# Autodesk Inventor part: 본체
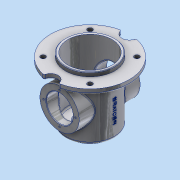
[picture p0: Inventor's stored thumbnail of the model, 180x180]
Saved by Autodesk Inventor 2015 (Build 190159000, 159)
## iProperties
Created: 2018-04
Part Number: 본체
Material: 알루미늄 6061
Document SubType Name: Modeling
Designer: SCD-A03
Density: 2.7 g/cm^3
Appearance: 알루미늄 - 평지
Mass: 1146.66 g
Surface Area: 1201.21 cm^2
Volume: 424.689 cm^3
Author: SCD-A03
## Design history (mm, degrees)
sketch "스케치1"
  geometry: C1 r 50 at (0, 0); 1 further point
  constraints: 1 centre point, 1 coincident
  dimensions: "d0" = 100 diameter of C1
extrude "돌출1" new body sketch "스케치1" distance "d1" = 128; taper "d2" = 0 deg
feature "쉘1" dims "d3" = 5
sketch "스케치2"
  geometry: C1 r 50 at (0, 0) reference; C2 r 40 at (0, 0)
  constraints: 1 centre point, 1 coincident
  dimensions: "d4" = 80 diameter of C2
extrude "돌출2" join sketch "스케치2" distance "d5" = 5; taper "d6" = 0 deg
sketch "스케치3"
  geometry: C1 r 50 at (0, 0) reference; C2 r 50 at (0, 0)
  constraints: 1 centre point, 1 coincident
  dimensions: "d7" = 100 diameter of C2
extrude "돌출3" join sketch "스케치3" distance "d8" = 8; taper "d9" = 0 deg
node "작업 평면1"
sketch "스케치4"
  geometry: C1 r 80 at (0, 0); C2 r 50 at (0, 0) reference; 1 further point
  constraints: 1 centre point, 1 coincident
  dimensions: "d11" = 160 diameter of C1
extrude "돌출4" join sketch "스케치4" distance "d12" = 10; taper "d13" = 0 deg
sketch "스케치5"
  geometry: C1 r 40 at (0, 0) reference; C2 r 27 at (0, 0)
  constraints: 1 centre point, 1 coincident
  dimensions: "d14" = 54 diameter of C2
extrude "돌출5" cut sketch "스케치5" stored distance "d15" = 10; taper "d16" = 0 deg
node "작업 평면2"
sketch "스케치6"
  geometry: L1 (-80, 120)-(80, 120) reference; L2 (0, 120)-(0, 60); C1 r 40 at (0, 60); 1 further point
  constraints: 2 end point, 1 centre point, 1 coincident, 1 midpoint, 1 vertical
  dimensions: "d18" = 60 distance of L2.start L2.end; "d19" = 80 diameter of C1
extrude "돌출6" join sketch "스케치6" stored distance "d20" = 10; taper "d21" = 0 deg
sketch "스케치7"
  geometry: C1 r 40 at (0, 0) reference; C2 r 27 at (0, 0); 1 further point
  constraints: 1 centre point, 1 coincident
  dimensions: "d22" = 54 diameter of C2
extrude "돌출7" cut sketch "스케치7" stored distance "d23" = 10; taper "d24" = 0 deg
sketch "스케치8" dims "d25" = 65
  geometry: L1 (-27, -52)-(27, -52) reference; L2 (-40, -65)-(40, -65) reference; L3 (-50, 50)-(50, 50) reference; L4 (-50, -60)-(50, -60) reference; C1 r 40 at (0, 0) reference; 7 further points
  constraints: 1 coincident, 1 vertical alignment, 8 other
  dimensions: "d28" = 360 deg dimension on point (0, 0) point (0, -32.5) (derived); "d30" = 52 distance from line of point (32.5, 0) L1
hole "구멍1" sketch "스케치8" at (0, -32.5), (32.5, 0), (0, 32.5), (-32.5, 0) diameter "d31" = 3.459; stored, may be unused: countersink angle "d35" = 90 deg, drill point angle "d37" = 118 deg; dims "d32" = 8, "d33" = 4, "d34" = 2, "d36" = 10
sketch "스케치9" dims "d38" = 65
  geometry: L1 (27, -62)-(27, -36) reference; C1 r 40 at (0, 0) reference; C2 r 80 at (0, 0) reference; C3 r 50 at (0, 0) reference; C4 r 80 at (0, 0) reference; 5 further points
  constraints: 1 coincident, 1 horizontal alignment, 7 other
  dimensions: "d41" = 360 deg dimension on point (0, 0) point (32.5, 0) (derived); "d43" = 5.5 distance from line of point (32.5, 0) L1
hole "구멍2" sketch "스케치9" at (32.5, 0), (0, 32.5), (-32.5, 0), (0, -32.5) diameter "d44" = 3.459; stored, may be unused: countersink angle "d48" = 90 deg, drill point angle "d50" = 118 deg; dims "d45" = 8, "d46" = 4, "d47" = 2, "d49" = 10
sketch "스케치10" dims "d52" = 135
  geometry: L1 (0, 0)-(0, -108.302); L2 (0, 0)-(95.068, -95.068); L3 (27, -62)-(-27, -62) reference; L4 (-40, -62)-(40, -62) reference; L5 (1.73, -62)-(-1.73, -62) reference; C1 r 50 at (0, 0) reference; C2 r 80 at (0, 0) reference; C3 r 1.73 at (-32.5, 0) reference; C4 r 1.73 at (32.5, 0) reference; C5 r 1.73 at (0, 32.5) reference; C6 r 1.73 at (0, -32.5) reference; C7 r 27 at (0, 0) reference; C8 r 40 at (0, 0) reference; C9 r 50 at (0, 0) reference; C10 r 80 at (0, 0) reference; C11 r 40 at (0, 0) reference; C12 r 50 at (0, 0) reference; C13 r 40 at (0, 0) reference; C14 r 1.73 at (0, -32.5) reference; C15 r 1.73 at (-32.5, 0) reference; C16 r 1.73 at (0, 32.5) reference; C17 r 1.73 at (32.5, 0) reference; C18 r 27 at (0, 0) reference; C19 r 50 at (0, 0) reference; 5 further points
  constraints: 4 end point, 1 coincident, 1 point on line, 1 vertical, 8 other
  dimensions: "d51" = 45 deg angle of L1 L2; "d55" = 360 deg dimension on point (0, 0) point (47.73, -47.73) (derived); "d57" = 33.06806 distance from line of L2.end L3; "d58" = 46.30152 distance from line of L1.end L3
hole "구멍3" sketch "스케치10" at (47.73, -47.73), (47.73, 47.73), (-47.73, 47.73), (-47.73, -47.73) diameter "d59" = 10; stored, may be unused: countersink angle "d63" = 90 deg, drill point angle "d65" = 118 deg; dims "d60" = 10, "d61" = 4, "d62" = 2, "d64" = 10
sketch "스케치11"
  geometry: C1 r 15 at (0, -80)
  constraints: 1 centre point
  dimensions: "d66" = 30 diameter of C1
extrude "돌출8" cut sketch "스케치11" stored distance "d68" = 10; taper "d69" = 0 deg
node "작업 평면3"
sketch "스케치12" dims "d11" = 160
  geometry: L1 (-78.594, 120)-(78.594, 120) reference; L2 (45, 8)-(45, 128) reference; L3 (-50, 0)-(-50, 110) reference; 2 further points
  constraints: 1 other
  dimensions: "d74" = 70 distance from line of L1 point (0, 50); "d76" = 45 distance from line of point (0, 50) L2
feature "엠보싱1" sketch "스케치12" dims "d77" = 0.5, "d78" = 0
chamfer "모따기1" distance "d79" = 1; stored, may be unused: second distance "d80" = 2, angle "d81" = 45 deg
fillet "모깎기1" dims "d82" = 5, "d83" = 3
node "솔리드1"
mirror "대칭1"
node "투영된 루프1"
node "투영된 루프2"
node "투영된 루프3"
node "투영된 루프4"
node "투영된 루프5"
other parameters: "d10" = -8, "d17" = -62
